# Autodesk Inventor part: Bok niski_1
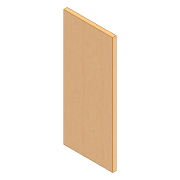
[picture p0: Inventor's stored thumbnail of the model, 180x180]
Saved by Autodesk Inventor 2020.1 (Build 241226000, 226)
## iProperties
Manager: www.cadconsulting.pl
Company: Fabian Stasiak CAD Consulting
Created: 2019-06
Part Number: Bok niski_1
Material: Ogólny
Document SubType Name: Modeling
Designer: F.Stasiak
Density: 1 g/cm^3
Appearance: Sosna żółta — pełna — barwiona na jasno — niski połysk
Author: F.Stasiak
Subject: Zbiór ćwiczeń. Autodesk Inventor 2020. Kurs podstawowy
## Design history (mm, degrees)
sketch "Szkic1"
  geometry: L1 (0, 0)-(-210, 0); L2 (-210, 0)-(-210, -500); L3 (-210, -500)-(0, -500); L4 (0, -500)-(0, 0)
  constraints: 8 end point, 2 parallel, 1 horizontal, 1 perpendicular
  dimensions: "d0" = 500 distance of L3.end L1.start; "d1" = 210 distance of L2.end L3.end
extrude "Wyciągnięcie proste1" new body sketch "Szkic1" distance "d2" = 15; taper "d3" = 0 deg
node "Bryła1"
